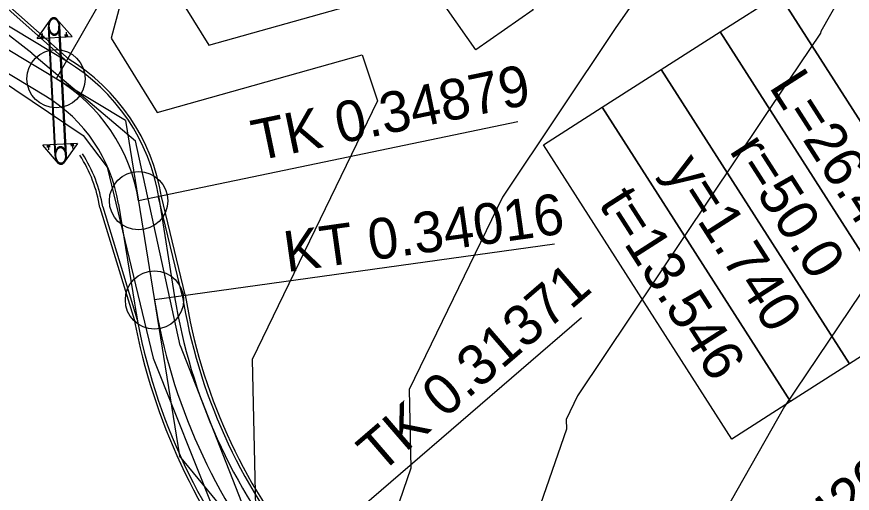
# Model space of a CAD drawing. Extents: x -549394 to -546608, y -1037055 to -1033629.
# Drawn here: x -547879.1 to -547807.4, y -1034661.9 to -1034621 of the extents above; entities that cross this region are included whole.
import ezdxf

# ---------------------------------------------------------------- set-up
doc = ezdxf.new("R2010")
doc.units = 0
for name, color, linetype in [('hlavni_vrst', 7, 'Continuous'), ('hrana_L', 7, 'Continuous'), ('norm_vrst', 7, 'Continuous'), ('POLYGONY_SITUACE_PO', 7, 'Continuous'), ('x_navrh_C21', 7, 'Continuous'), ('x_osa_C21', 7, 'Continuous'), ('x_popis_oblouky_C21', 7, 'Continuous'), ('x_popis_velky_C21', 7, 'Continuous'), ('x_propustek', 7, 'Continuous')]:
    doc.layers.add(name, color=color, linetype=linetype)

msp = doc.modelspace()

# ---------------------------------------------------------------- linework, layer by layer
at = {"layer": 'hlavni_vrst'}
for p, q in [((-547797.206, -1034630.702), (-547813.158, -1034654.449)), ((-547813.158, -1034654.449), (-547828.029, -1034680.562))]:
    msp.add_line(p, q, dxfattribs=at)
at = {"layer": 'hrana_L'}
for p, q in [((-547877.75, -1034624.13), (-547888.02, -1034616.15)), ((-547888.78, -1034620.79), (-547873.35, -1034631.21)), ((-547877.75, -1034624.13), (-547868.85, -1034631.65)), ((-547873.35, -1034631.21), (-547871.3, -1034633.92)), ((-547865.04, -1034649.22), (-547868.85, -1034631.65)), ((-547871.3, -1034633.92), (-547867.33, -1034650.32)), ((-547865.04, -1034649.22), (-547859.51, -1034663.34)), ((-547867.33, -1034650.32), (-547861.32, -1034665.38))]:
    msp.add_line(p, q, dxfattribs=at)
at = {"layer": 'norm_vrst'}
for p, q in [((-547784.032, -1034575.823), (-547810.04, -1034622.26)), ((-547824.566, -1034617.477), (-547827.692, -1034622.021)), ((-547870.184, -1034619.954), (-547870.954, -1034622.829)), ((-547864.54, -1034620.272), (-547862.569, -1034623.454)), ((-547862.569, -1034623.454), (-547850.018, -1034619.923)), ((-547827.692, -1034622.021), (-547837.373, -1034636.492)), ((-547810.082, -1034622.416), (-547812.8, -1034626.461)), ((-547810.04, -1034622.26), (-547810.082, -1034622.416)), ((-547870.954, -1034622.829), (-547866.992, -1034629.226)), ((-547866.992, -1034629.226), (-547849.403, -1034624.278)), ((-547849.403, -1034624.278), (-547848.081, -1034628.213)), ((-547812.8, -1034626.461), (-547830.923, -1034653.552)), ((-547848.081, -1034628.213), (-547858.844, -1034650.409)), ((-547837.373, -1034636.492), (-547845.375, -1034652.994)), ((-547858.844, -1034650.409), (-547858.576, -1034663.106)), ((-547845.375, -1034652.994), (-547845.232, -1034659.757)), ((-547830.923, -1034653.552), (-547831.906, -1034655.578)), ((-547831.906, -1034655.578), (-547831.888, -1034656.409)), ((-547831.888, -1034656.409), (-547839.521, -1034678.541)), ((-547845.232, -1034659.757), (-547849.177, -1034671.197))]:
    msp.add_line(p, q, dxfattribs=at)
at = {"layer": 'POLYGONY_SITUACE_PO'}
for centre in [(-547875.675, -1034626.326), (-547868.598, -1034636.8), (-547867.23, -1034645.316)]:
    msp.add_circle(centre, 2.5, dxfattribs=at)
at = {"layer": 'x_navrh_C21'}
for p, q in [((-547880.295, -1034619.905), (-547874.698, -1034624.882)), ((-547880.147, -1034619.702), (-547874.549, -1034624.679)), ((-547864.844, -1034644.913), (-547866.878, -1034636.484)), ((-547864.598, -1034644.864), (-547866.633, -1034636.435)), ((-547871.918, -1034637.385), (-547868.949, -1034647.075)), ((-547871.673, -1034637.328), (-547868.706, -1034647.015))]:
    msp.add_line(p, q, dxfattribs=at)
for centre, radius, start, end in [((-547883.408, -1034639.179), 17, 9.1607, 58.8846), ((-547883.408, -1034639.179), 11.63, 8.87559, 32.6981), ((-547883.408, -1034639.179), 11.88, 8.96201, 32.69647), ((-547817.863, -1034637.385), 47.58, 189.10362, 219.46464), ((-547817.863, -1034637.385), 47.33, 189.09183, 219.47481), ((-547817.863, -1034637.385), 52, 190.67939, 219.44455)]:
    msp.add_arc(centre, radius, start, end, dxfattribs=at)
at = {"layer": 'x_osa_C21'}
msp.add_line((-547869.704, -1034629.919), (-547865.081, -1034658.691), dxfattribs=at)
for points in [[(-547869.704, -1034629.919), (-547885.557, -1034620.381)], [(-547815.621, -1034735.245), (-547833.773, -1034696.745), (-547865.081, -1034658.691)]]:
    msp.add_lwpolyline(points, dxfattribs=at)
for centre, radius, start, end in [((-547883.408, -1034639.179), 15, 9.12691, 58.9655), ((-547817.863, -1034637.385), 50, 189.12691, 219.44455)]:
    msp.add_arc(centre, radius, start, end, dxfattribs=at)
at = {"layer": 'x_popis_oblouky_C21'}
for points in [[(-547857.006, -1034593.764), (-547875.675, -1034626.326)], [(-547836.055, -1034630.033), (-547868.598, -1034636.8)], [(-547832.892, -1034640.512), (-547867.23, -1034645.316)], [(-547830.601, -1034646.849), (-547856.475, -1034669.151)]]:
    msp.add_lwpolyline(points, dxfattribs=at)
for points in [[(-547851.966, -1034595.837), (-547834.745, -1034620.402), (-547839.658, -1034623.846), (-547856.879, -1034599.281)], [(-547808.585, -1034615.826), (-547792.422, -1034641.1), (-547797.477, -1034644.332), (-547813.639, -1034619.058)], [(-547813.639, -1034619.058), (-547797.477, -1034644.332), (-547802.532, -1034647.565), (-547818.694, -1034622.291)], [(-547818.694, -1034622.291), (-547802.532, -1034647.565), (-547807.587, -1034650.797), (-547823.749, -1034625.523)], [(-547823.749, -1034625.523), (-547807.587, -1034650.797), (-547812.642, -1034654.03), (-547828.804, -1034628.756)], [(-547828.804, -1034628.756), (-547812.642, -1034654.03), (-547817.697, -1034657.262), (-547833.859, -1034631.988)]]:
    msp.add_lwpolyline(points, close=True, dxfattribs=at)
at = {"layer": 'x_popis_velky_C21'}
for p, q in [((-547874.773, -1034624.827), (-547881.041, -1034621.055)), ((-547876.577, -1034627.826), (-547882.846, -1034624.054)), ((-547866.87, -1034636.522), (-547865.502, -1034645.038)), ((-547870.326, -1034637.077), (-547868.958, -1034645.594))]:
    msp.add_line(p, q, dxfattribs=at)
for centre, radius, start, end in [((-547883.408, -1034639.179), 16.75, 9.12691, 58.9655), ((-547883.408, -1034639.179), 13.25, 9.12691, 58.9655), ((-547817.863, -1034637.385), 48.25, 189.12691, 219.44455), ((-547817.863, -1034637.385), 51.75, 189.12691, 219.44455)]:
    msp.add_arc(centre, radius, start, end, dxfattribs=at)
at = {"layer": 'x_propustek'}
for p, q in [((-547877.295, -1034622.862), (-547876.092, -1034621.173)), ((-547875.669, -1034621.151), (-547876.092, -1034621.173)), ((-547875.669, -1034621.151), (-547874.299, -1034622.708)), ((-547876.822, -1034622.838), (-547876.843, -1034622.438)), ((-547875.763, -1034632.934), (-547876.333, -1034621.863)), ((-547875.689, -1034632.93), (-547876.258, -1034621.859)), ((-547874.863, -1034632.888), (-547875.432, -1034621.817)), ((-547874.788, -1034632.884), (-547875.357, -1034621.813)), ((-547874.77, -1034622.732), (-547874.79, -1034622.332)), ((-547877.295, -1034622.862), (-547874.299, -1034622.708)), ((-547876.922, -1034622.843), (-547876.932, -1034622.643)), ((-547876.722, -1034622.832), (-547876.733, -1034622.633)), ((-547874.87, -1034622.737), (-547874.88, -1034622.537)), ((-547874.67, -1034622.727), (-547874.68, -1034622.527)), ((-547873.826, -1034631.885), (-547876.822, -1034632.039)), ((-547875.452, -1034633.596), (-547876.822, -1034632.039)), ((-547876.451, -1034632.02), (-547876.441, -1034632.219)), ((-547876.351, -1034632.015), (-547876.331, -1034632.414)), ((-547876.251, -1034632.01), (-547876.241, -1034632.209)), ((-547873.826, -1034631.885), (-547875.029, -1034633.574)), ((-547874.398, -1034631.914), (-547874.388, -1034632.114)), ((-547874.299, -1034631.909), (-547874.278, -1034632.308)), ((-547874.199, -1034631.904), (-547874.188, -1034632.104)), ((-547875.452, -1034633.596), (-547875.029, -1034633.574))]:
    msp.add_line(p, q, dxfattribs=at)
for points in [[(-547875.884, -1034621.087), (-547875.9, -1034621.088), (-547875.915, -1034621.09), (-547875.946, -1034621.096), (-547875.962, -1034621.1), (-547876.007, -1034621.117), (-547876.036, -1034621.132), (-547876.121, -1034621.191), (-547876.172, -1034621.248), (-547876.258, -1034621.393), (-547876.29, -1034621.479), (-547876.33, -1034621.663), (-547876.338, -1034621.763), (-547876.328, -1034621.964), (-547876.31, -1034622.062), (-547876.25, -1034622.241), (-547876.209, -1034622.323), (-547876.109, -1034622.458), (-547876.052, -1034622.51), (-547875.977, -1034622.552), (-547875.962, -1034622.559), (-547875.931, -1034622.571), (-547875.916, -1034622.576), (-547875.869, -1034622.588), (-547875.838, -1034622.591), (-547875.806, -1034622.589)], [(-547875.88, -1034621.162), (-547875.904, -1034621.163), (-547875.928, -1034621.168), (-547875.975, -1034621.185), (-547875.998, -1034621.197), (-547876.044, -1034621.229), (-547876.067, -1034621.25), (-547876.11, -1034621.298), (-547876.131, -1034621.327), (-547876.169, -1034621.391), (-547876.186, -1034621.427), (-547876.215, -1034621.503), (-547876.227, -1034621.544), (-547876.255, -1034621.672), (-547876.263, -1034621.765), (-547876.253, -1034621.954), (-547876.236, -1034622.045), (-547876.195, -1034622.17), (-547876.179, -1034622.209), (-547876.142, -1034622.282), (-547876.121, -1034622.316), (-547876.077, -1034622.376), (-547876.053, -1034622.402), (-547876.005, -1034622.446), (-547875.98, -1034622.464), (-547875.931, -1034622.491), (-547875.907, -1034622.501), (-547875.858, -1034622.513), (-547875.834, -1034622.515), (-547875.786, -1034622.513), (-547875.763, -1034622.508), (-547875.716, -1034622.491), (-547875.692, -1034622.479), (-547875.646, -1034622.447), (-547875.624, -1034622.427), (-547875.58, -1034622.378), (-547875.559, -1034622.35), (-547875.521, -1034622.285), (-547875.504, -1034622.249), (-547875.475, -1034622.173), (-547875.463, -1034622.132), (-547875.435, -1034622.004), (-547875.427, -1034621.911), (-547875.437, -1034621.723), (-547875.454, -1034621.631), (-547875.495, -1034621.506), (-547875.512, -1034621.467), (-547875.549, -1034621.394), (-547875.569, -1034621.36), (-547875.614, -1034621.3), (-547875.637, -1034621.274), (-547875.686, -1034621.23), (-547875.71, -1034621.212), (-547875.759, -1034621.185), (-547875.784, -1034621.175), (-547875.832, -1034621.163), (-547875.856, -1034621.161), (-547875.88, -1034621.162)], [(-547875.806, -1034622.589), (-547875.791, -1034622.588), (-547875.775, -1034622.586), (-547875.744, -1034622.58), (-547875.729, -1034622.576), (-547875.684, -1034622.559), (-547875.654, -1034622.544), (-547875.57, -1034622.485), (-547875.519, -1034622.428), (-547875.433, -1034622.283), (-547875.401, -1034622.197), (-547875.36, -1034622.013), (-547875.352, -1034621.914), (-547875.363, -1034621.712), (-547875.381, -1034621.614), (-547875.44, -1034621.435), (-547875.481, -1034621.353), (-547875.581, -1034621.218), (-547875.638, -1034621.166), (-547875.713, -1034621.125), (-547875.728, -1034621.117), (-547875.759, -1034621.105), (-547875.775, -1034621.1), (-547875.821, -1034621.089), (-547875.853, -1034621.085), (-547875.884, -1034621.087)], [(-547875.314, -1034632.158), (-547875.33, -1034632.158), (-547875.346, -1034632.16), (-547875.377, -1034632.167), (-547875.392, -1034632.171), (-547875.437, -1034632.187), (-547875.466, -1034632.203), (-547875.551, -1034632.262), (-547875.602, -1034632.319), (-547875.688, -1034632.464), (-547875.72, -1034632.549), (-547875.761, -1034632.734), (-547875.769, -1034632.833), (-547875.758, -1034633.034), (-547875.74, -1034633.132), (-547875.681, -1034633.312), (-547875.64, -1034633.393), (-547875.54, -1034633.529), (-547875.483, -1034633.58), (-547875.408, -1034633.622), (-547875.392, -1034633.629), (-547875.362, -1034633.642), (-547875.346, -1034633.646), (-547875.3, -1034633.658), (-547875.268, -1034633.661), (-547875.237, -1034633.659)], [(-547875.241, -1034633.585), (-547875.217, -1034633.583), (-547875.193, -1034633.579), (-547875.146, -1034633.562), (-547875.123, -1034633.55), (-547875.077, -1034633.517), (-547875.054, -1034633.497), (-547875.011, -1034633.448), (-547874.99, -1034633.42), (-547874.952, -1034633.355), (-547874.935, -1034633.32), (-547874.906, -1034633.243), (-547874.893, -1034633.202), (-547874.865, -1034633.074), (-547874.858, -1034632.981), (-547874.867, -1034632.793), (-547874.885, -1034632.701), (-547874.926, -1034632.577), (-547874.942, -1034632.537), (-547874.979, -1034632.464), (-547874.999, -1034632.431), (-547875.044, -1034632.37), (-547875.068, -1034632.344), (-547875.116, -1034632.3), (-547875.14, -1034632.283), (-547875.19, -1034632.255), (-547875.214, -1034632.245), (-547875.263, -1034632.234), (-547875.287, -1034632.231), (-547875.335, -1034632.234), (-547875.358, -1034632.238), (-547875.405, -1034632.255), (-547875.428, -1034632.267), (-547875.475, -1034632.3), (-547875.497, -1034632.32), (-547875.541, -1034632.369), (-547875.561, -1034632.397), (-547875.599, -1034632.462), (-547875.616, -1034632.497), (-547875.646, -1034632.574), (-547875.658, -1034632.615), (-547875.686, -1034632.743), (-547875.693, -1034632.836), (-547875.684, -1034633.024), (-547875.666, -1034633.116), (-547875.625, -1034633.24), (-547875.609, -1034633.28), (-547875.572, -1034633.353), (-547875.552, -1034633.386), (-547875.507, -1034633.447), (-547875.484, -1034633.473), (-547875.435, -1034633.517), (-547875.411, -1034633.534), (-547875.362, -1034633.562), (-547875.337, -1034633.572), (-547875.289, -1034633.583), (-547875.265, -1034633.586), (-547875.241, -1034633.585)], [(-547875.237, -1034633.659), (-547875.221, -1034633.659), (-547875.205, -1034633.657), (-547875.174, -1034633.65), (-547875.159, -1034633.646), (-547875.114, -1034633.63), (-547875.085, -1034633.614), (-547875, -1034633.555), (-547874.949, -1034633.498), (-547874.863, -1034633.353), (-547874.831, -1034633.268), (-547874.791, -1034633.083), (-547874.783, -1034632.984), (-547874.793, -1034632.783), (-547874.811, -1034632.685), (-547874.871, -1034632.505), (-547874.911, -1034632.424), (-547875.011, -1034632.288), (-547875.069, -1034632.237), (-547875.144, -1034632.195), (-547875.159, -1034632.188), (-547875.189, -1034632.175), (-547875.205, -1034632.171), (-547875.251, -1034632.159), (-547875.283, -1034632.156), (-547875.314, -1034632.158)]]:
    msp.add_open_spline(points, degree=3, dxfattribs=at)

# ---------------------------------------------------------------- texts
at = {"layer": 'x_popis_oblouky_C21'}
for s, rotation, p in [('TK 0.34879', 11.74661, (-547858.46, -1034633.39)), ('L=26.457', 302.61972, (-547814.555, -1034627.01)), ('r=50.0', 302.61972, (-547817.958, -1034632.507)), ('y=1.740', 302.61972, (-547823.457, -1034634.224)), ('t=13.546', 302.61972, (-547829.185, -1034637.058)), ('KT 0.34016', 7.96342, (-547855.874, -1034642.932)), ('TK 0.31371', 40.75909, (-547847.87, -1034660.311)), ('KT 0.28420', 39.99163, (-547822.042, -1034676.611))]:
    msp.add_text(s, height=3.5, rotation=rotation, dxfattribs=at).set_placement(p)

doc.saveas('drawing.dxf')
